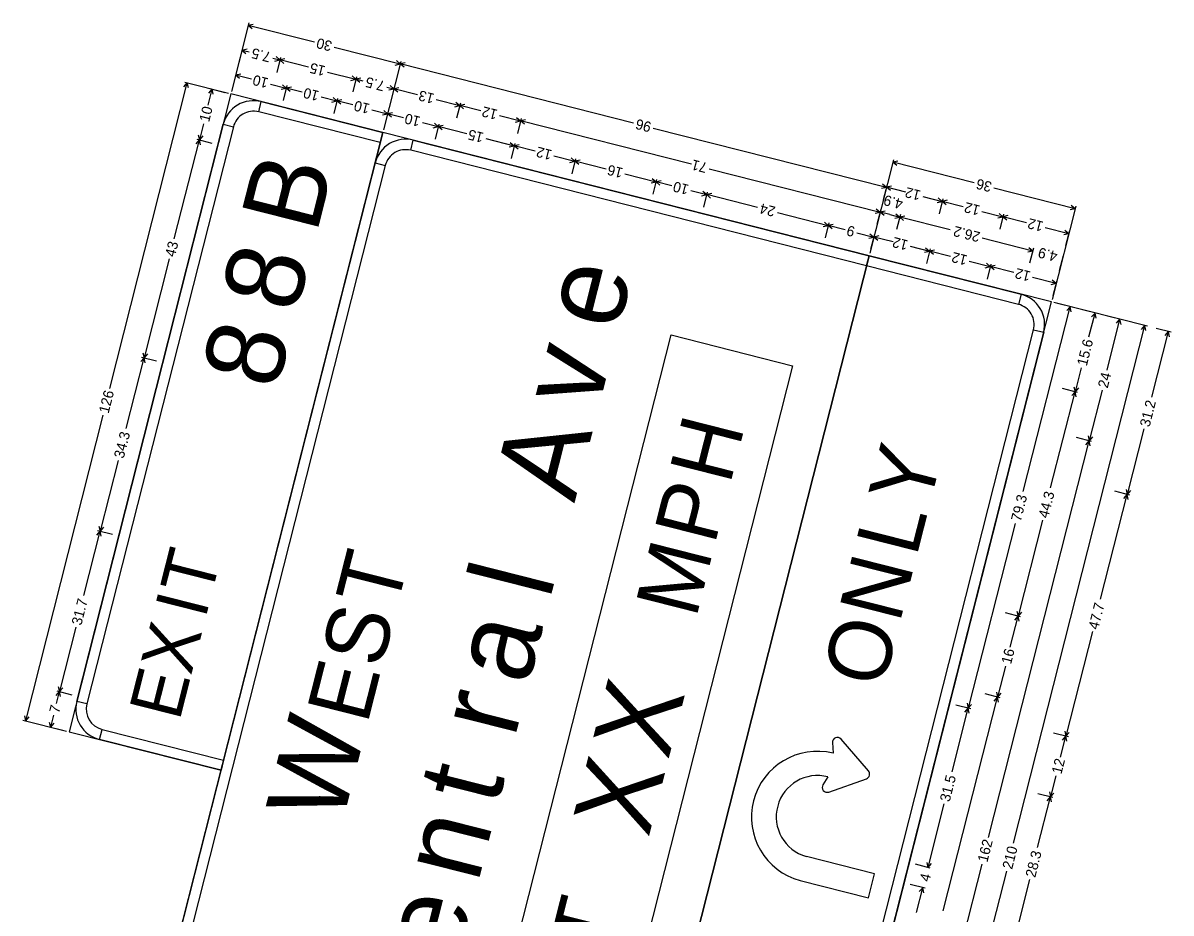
# Model space of a CAD drawing. Extents: x 670003 to 670131, y 737764 to 738002.
# Drawn here: x 670003.1 to 670058, y 737872.3 to 737914.9 of the extents above; entities that cross this region are included whole.
import ezdxf

# ---------------------------------------------------------------- set-up
doc = ezdxf.new("R2010")
doc.units = 0
doc.layers.add('R_SIGN', color=7, linetype='Continuous')

msp = doc.modelspace()

# ---------------------------------------------------------------- linework, layer by layer
at = {"layer": 'R_SIGN'}
for p, q in [((670013.91, 737914.946), (670013.078, 737911.666)), ((670014.12, 737914.879), (670013.88, 737914.826)), ((670017.044, 737914.024), (670013.88, 737914.826)), ((670014.066, 737914.666), (670013.88, 737914.826)), ((670013.608, 737913.753), (670013.426, 737913.038)), ((670013.818, 737913.686), (670013.577, 737913.634)), ((670013.917, 737913.548), (670013.577, 737913.634)), ((670013.764, 737913.473), (670013.577, 737913.634)), ((670017.986, 737913.785), (670021.15, 737912.982)), ((670015.055, 737913.259), (670015.395, 737913.173)), ((670015.155, 737913.12), (670015.395, 737913.173)), ((670015.209, 737913.334), (670015.395, 737913.173)), ((670015.425, 737913.292), (670015.244, 737912.577)), ((670015.635, 737913.225), (670015.395, 737913.173)), ((670016.761, 737912.826), (670015.395, 737913.173)), ((670015.581, 737913.012), (670015.395, 737913.173)), ((670021.18, 737913.102), (670020.348, 737909.822)), ((670021.18, 737913.102), (670020.348, 737909.822)), ((670020.909, 737912.93), (670021.15, 737912.982)), ((670020.964, 737913.143), (670021.15, 737912.982)), ((670021.39, 737913.035), (670021.15, 737912.982)), ((670032.305, 737910.153), (670021.15, 737912.982)), ((670021.336, 737912.822), (670021.15, 737912.982)), ((670013.305, 737912.561), (670013.124, 737911.845)), ((670013.515, 737912.494), (670013.275, 737912.441)), ((670014.036, 737912.248), (670013.275, 737912.441)), ((670013.461, 737912.281), (670013.275, 737912.441)), ((670017.664, 737912.597), (670019.03, 737912.251)), ((670007.253, 737897.455), (670010.961, 737912.076)), ((670010.801, 737911.89), (670010.961, 737912.076)), ((670010.842, 737912.106), (670012.929, 737911.577)), ((670011.014, 737911.836), (670010.961, 737912.076)), ((670014.937, 737912.02), (670015.698, 737911.827)), ((670015.512, 737911.987), (670015.698, 737911.827)), ((670015.729, 737911.946), (670015.547, 737911.23)), ((670015.939, 737911.879), (670015.698, 737911.827)), ((670018.79, 737912.198), (670019.03, 737912.251)), ((670018.844, 737912.412), (670019.03, 737912.251)), ((670019.06, 737912.37), (670018.879, 737911.655)), ((670019.06, 737912.37), (670018.879, 737911.655)), ((670019.27, 737912.303), (670019.03, 737912.251)), ((670019.37, 737912.165), (670019.03, 737912.251)), ((670019.216, 737912.09), (670019.03, 737912.251)), ((670020.507, 737911.876), (670020.847, 737911.79)), ((670020.661, 737911.951), (670020.847, 737911.79)), ((670020.878, 737911.909), (670020.696, 737911.194)), ((670020.878, 737911.909), (670020.696, 737911.194)), ((670013.048, 737911.547), (670005.304, 737881.014)), ((670011.961, 737911.012), (670012.154, 737911.774)), ((670011.993, 737911.587), (670012.154, 737911.774)), ((670012.035, 737911.804), (670012.75, 737911.622)), ((670012.206, 737911.533), (670012.154, 737911.774)), ((670020.318, 737909.703), (670013.048, 737911.547)), ((670015.458, 737911.774), (670015.698, 737911.827)), ((670016.46, 737911.634), (670015.698, 737911.827)), ((670015.885, 737911.666), (670015.698, 737911.827)), ((670017.36, 737911.405), (670018.122, 737911.212)), ((670017.935, 737911.373), (670018.122, 737911.212)), ((670018.152, 737911.331), (670017.97, 737910.616)), ((670018.152, 737911.331), (670017.97, 737910.616)), ((670020.607, 737911.737), (670020.847, 737911.79)), ((670021.088, 737911.843), (670020.847, 737911.79)), ((670021.971, 737911.505), (670020.847, 737911.79)), ((670021.034, 737911.629), (670020.847, 737911.79)), ((670014.379, 737910.693), (670014.502, 737911.178)), ((670017.881, 737911.16), (670018.122, 737911.212)), ((670018.362, 737911.265), (670018.122, 737911.212)), ((670018.883, 737911.019), (670018.122, 737911.212)), ((670018.308, 737911.051), (670018.122, 737911.212)), ((670019.783, 737910.791), (670020.545, 737910.597)), ((670022.874, 737911.276), (670023.998, 737910.991)), ((670023.757, 737910.938), (670023.998, 737910.991)), ((670023.811, 737911.152), (670023.998, 737910.991)), ((670024.028, 737911.11), (670023.846, 737910.395)), ((670024.238, 737911.044), (670023.998, 737910.991)), ((670025.002, 737910.736), (670023.998, 737910.991)), ((670024.184, 737910.83), (670023.998, 737910.991)), ((670020.305, 737910.545), (670020.545, 737910.597)), ((670020.359, 737910.758), (670020.545, 737910.597)), ((670020.575, 737910.717), (670020.394, 737910.001)), ((670020.575, 737910.717), (670020.394, 737910.001)), ((670020.785, 737910.65), (670020.545, 737910.597)), ((670021.306, 737910.404), (670020.545, 737910.597)), ((670020.731, 737910.437), (670020.545, 737910.597)), ((670025.901, 737910.508), (670026.905, 737910.253)), ((670026.665, 737910.201), (670026.905, 737910.253)), ((670026.719, 737910.414), (670026.905, 737910.253)), ((670026.936, 737910.373), (670026.754, 737909.657)), ((670026.936, 737910.373), (670026.754, 737909.657)), ((670027.146, 737910.306), (670026.905, 737910.253)), ((670035.084, 737908.179), (670026.905, 737910.253)), ((670027.092, 737910.093), (670026.905, 737910.253)), ((670020.318, 737909.703), (670007.411, 737858.814)), ((670011.732, 737910.112), (670011.539, 737909.35)), ((670012.574, 737879.17), (670020.318, 737909.703)), ((670012.679, 737910.093), (670013.164, 737909.97)), ((670043.581, 737903.803), (670020.318, 737909.703)), ((670022.207, 737910.176), (670022.968, 737909.983)), ((670022.728, 737909.93), (670022.968, 737909.983)), ((670022.782, 737910.144), (670022.968, 737909.983)), ((670022.998, 737910.102), (670022.817, 737909.387)), ((670023.208, 737910.035), (670022.968, 737909.983)), ((670024.334, 737909.636), (670022.968, 737909.983)), ((670023.154, 737909.822), (670022.968, 737909.983)), ((670033.258, 737909.912), (670044.413, 737907.082)), ((670010.339, 737904.618), (670011.539, 737909.35)), ((670011.378, 737909.164), (670011.539, 737909.35)), ((670011.42, 737909.381), (670012.136, 737909.199)), ((670011.42, 737909.381), (670012.136, 737909.199)), ((670011.487, 737909.591), (670011.539, 737909.35)), ((670011.7, 737909.537), (670011.539, 737909.35)), ((670011.592, 737909.11), (670011.539, 737909.35)), ((670021.649, 737908.85), (670021.772, 737909.334)), ((670025.237, 737909.407), (670026.603, 737909.061)), ((670026.417, 737909.222), (670026.603, 737909.061)), ((670026.633, 737909.18), (670026.452, 737908.465)), ((670026.363, 737909.008), (670026.603, 737909.061)), ((670026.843, 737909.114), (670026.603, 737909.061)), ((670027.608, 737908.806), (670026.603, 737909.061)), ((670026.789, 737908.9), (670026.603, 737909.061)), ((670028.506, 737908.578), (670029.511, 737908.323)), ((670019.949, 737908.249), (670020.434, 737908.126)), ((670029.271, 737908.271), (670029.511, 737908.323)), ((670029.325, 737908.484), (670029.511, 737908.323)), ((670029.541, 737908.443), (670029.36, 737907.727)), ((670029.751, 737908.376), (670029.511, 737908.323)), ((670030.996, 737907.947), (670029.511, 737908.323)), ((670029.697, 737908.163), (670029.511, 737908.323)), ((670044.746, 737908.394), (670043.612, 737903.922)), ((670044.956, 737908.328), (670044.716, 737908.275)), ((670048.602, 737907.289), (670044.716, 737908.275)), ((670044.902, 737908.114), (670044.716, 737908.275)), ((670031.903, 737907.717), (670033.388, 737907.34)), ((670033.202, 737907.501), (670033.388, 737907.34)), ((670035.932, 737907.964), (670044.111, 737905.89)), ((670033.148, 737907.288), (670033.388, 737907.34)), ((670033.418, 737907.459), (670033.237, 737906.744)), ((670033.629, 737907.393), (670033.388, 737907.34)), ((670034.15, 737907.147), (670033.388, 737907.34)), ((670033.574, 737907.179), (670033.388, 737907.34)), ((670044.443, 737907.202), (670043.612, 737903.922)), ((670044.173, 737907.03), (670044.413, 737907.082)), ((670044.227, 737907.243), (670044.413, 737907.082)), ((670044.443, 737907.202), (670044.262, 737906.486)), ((670044.654, 737907.135), (670044.413, 737907.082)), ((670045.343, 737906.846), (670044.413, 737907.082)), ((670044.599, 737906.922), (670044.413, 737907.082)), ((670049.553, 737907.048), (670053.439, 737906.063)), ((670035.05, 737906.919), (670035.811, 737906.726)), ((670035.571, 737906.673), (670035.811, 737906.726)), ((670035.625, 737906.886), (670035.811, 737906.726)), ((670035.842, 737906.845), (670035.66, 737906.129)), ((670036.052, 737906.778), (670035.811, 737906.726)), ((670038.244, 737906.109), (670035.811, 737906.726)), ((670035.998, 737906.565), (670035.811, 737906.726)), ((670046.149, 737906.642), (670047.079, 737906.406)), ((670046.839, 737906.354), (670047.079, 737906.406)), ((670046.893, 737906.567), (670047.079, 737906.406)), ((670047.109, 737906.526), (670046.928, 737905.81)), ((670047.319, 737906.459), (670047.079, 737906.406)), ((670048.084, 737906.151), (670047.079, 737906.406)), ((670047.265, 737906.246), (670047.079, 737906.406)), ((670039.195, 737905.867), (670041.627, 737905.25)), ((670043.87, 737905.837), (670044.111, 737905.89)), ((670043.925, 737906.051), (670044.111, 737905.89)), ((670044.141, 737906.009), (670043.96, 737905.294)), ((670044.141, 737906.009), (670043.96, 737905.294)), ((670044.351, 737905.942), (670044.111, 737905.89)), ((670044.58, 737905.771), (670044.111, 737905.89)), ((670044.297, 737905.729), (670044.111, 737905.89)), ((670048.982, 737905.924), (670049.987, 737905.669)), ((670049.801, 737905.83), (670049.987, 737905.669)), ((670053.47, 737906.182), (670052.335, 737901.71)), ((670053.199, 737906.01), (670053.439, 737906.063)), ((670053.253, 737906.223), (670053.439, 737906.063)), ((670041.441, 737905.411), (670041.627, 737905.25)), ((670041.658, 737905.37), (670041.476, 737904.654)), ((670041.658, 737905.37), (670041.476, 737904.654)), ((670041.868, 737905.303), (670041.627, 737905.25)), ((670044.58, 737905.771), (670045.05, 737905.652)), ((670044.809, 737905.599), (670045.05, 737905.652)), ((670044.863, 737905.812), (670045.05, 737905.652)), ((670045.08, 737905.771), (670044.898, 737905.056)), ((670045.29, 737905.704), (670045.05, 737905.652)), ((670047.468, 737905.038), (670045.05, 737905.652)), ((670045.236, 737905.491), (670045.05, 737905.652)), ((670049.746, 737905.616), (670049.987, 737905.669)), ((670050.017, 737905.788), (670049.836, 737905.073)), ((670050.017, 737905.788), (670049.836, 737905.073)), ((670050.227, 737905.722), (670049.987, 737905.669)), ((670051.11, 737905.384), (670049.987, 737905.669)), ((670050.173, 737905.508), (670049.987, 737905.669)), ((670041.387, 737905.198), (670041.627, 737905.25)), ((670042.435, 737905.046), (670041.627, 737905.25)), ((670041.814, 737905.09), (670041.627, 737905.25)), ((670043.001, 737904.902), (670043.808, 737904.697)), ((670043.622, 737904.858), (670043.808, 737904.697)), ((670043.839, 737904.817), (670043.657, 737904.101)), ((670043.839, 737904.817), (670043.657, 737904.101)), ((670044.049, 737904.75), (670043.808, 737904.697)), ((670052.013, 737905.155), (670053.137, 737904.87)), ((670052.897, 737904.817), (670053.137, 737904.87)), ((670052.951, 737905.031), (670053.137, 737904.87)), ((670053.167, 737904.989), (670052.986, 737904.274)), ((670043.568, 737904.645), (670043.808, 737904.697)), ((670044.738, 737904.461), (670043.808, 737904.697)), ((670043.995, 737904.537), (670043.808, 737904.697)), ((670045.544, 737904.257), (670046.474, 737904.021)), ((670046.288, 737904.182), (670046.474, 737904.021)), ((670048.993, 737904.652), (670051.411, 737904.038)), ((670051.225, 737904.199), (670051.411, 737904.038)), ((670010.093, 737903.65), (670008.893, 737898.918)), ((670030.675, 737852.914), (670043.581, 737903.803)), ((670043.581, 737903.803), (670030.675, 737852.914)), ((670052.305, 737901.59), (670043.581, 737903.803)), ((670046.234, 737903.969), (670046.474, 737904.021)), ((670046.504, 737904.14), (670046.323, 737903.425)), ((670046.714, 737904.074), (670046.474, 737904.021)), ((670047.479, 737903.766), (670046.474, 737904.021)), ((670046.66, 737903.861), (670046.474, 737904.021)), ((670051.171, 737903.986), (670051.411, 737904.038)), ((670051.441, 737904.158), (670051.26, 737903.442)), ((670051.441, 737904.158), (670051.26, 737903.442)), ((670052.865, 737903.796), (670052.683, 737903.081)), ((670048.377, 737903.539), (670049.382, 737903.284)), ((670049.142, 737903.231), (670049.382, 737903.284)), ((670049.196, 737903.444), (670049.382, 737903.284)), ((670049.412, 737903.403), (670049.231, 737902.687)), ((670049.412, 737903.403), (670049.231, 737902.687)), ((670049.622, 737903.336), (670049.382, 737903.284)), ((670050.506, 737902.999), (670049.382, 737903.284)), ((670049.568, 737903.123), (670049.382, 737903.284)), ((670051.408, 737902.77), (670052.532, 737902.485)), ((670052.346, 737902.645), (670052.532, 737902.485)), ((670052.562, 737902.604), (670052.381, 737901.888)), ((670052.292, 737902.432), (670052.532, 737902.485)), ((670039.399, 737850.702), (670052.305, 737901.59)), ((670050.851, 737901.959), (670050.728, 737901.474)), ((670056.897, 737900.426), (670052.424, 737901.56)), ((670053.319, 737901.333), (670052.603, 737901.515)), ((670050.955, 737892.512), (670053.2, 737901.363)), ((670053.039, 737901.177), (670053.2, 737901.363)), ((670053.252, 737901.123), (670053.2, 737901.363)), ((670054.511, 737901.031), (670053.796, 737901.212)), ((670054.102, 737899.917), (670054.392, 737901.061)), ((670054.231, 737900.875), (670054.392, 737901.061)), ((670054.445, 737900.821), (670054.392, 737901.061)), ((670055.704, 737900.728), (670054.989, 737900.91)), ((670050.493, 737875.679), (670056.777, 737900.456)), ((670054.968, 737898.326), (670055.585, 737900.759)), ((670055.424, 737900.572), (670055.585, 737900.759)), ((670055.637, 737900.518), (670055.585, 737900.759)), ((670056.617, 737900.27), (670056.777, 737900.456)), ((670056.83, 737900.216), (670056.777, 737900.456)), ((670024.153, 737860.758), (670034.11, 737900.015)), ((670034.11, 737900.015), (670039.925, 737898.54)), ((670051.452, 737900.259), (670051.936, 737900.136)), ((670057.114, 737897.029), (670057.91, 737900.169)), ((670058.03, 737900.139), (670057.314, 737900.32)), ((670057.75, 737899.983), (670057.91, 737900.169)), ((670057.963, 737899.928), (670057.91, 737900.169)), ((670008.034, 737895.528), (670008.893, 737898.918)), ((670008.733, 737898.732), (670008.893, 737898.918)), ((670008.774, 737898.948), (670009.49, 737898.767)), ((670008.841, 737899.159), (670008.893, 737898.918)), ((670009.054, 737899.104), (670008.893, 737898.918)), ((670008.946, 737898.678), (670008.893, 737898.918)), ((670039.925, 737898.54), (670029.969, 737859.283)), ((670053.726, 737898.435), (670053.436, 737897.29)), ((670052.269, 737892.692), (670053.436, 737897.29)), ((670053.555, 737897.26), (670052.84, 737897.442)), ((670053.555, 737897.26), (670052.84, 737897.442)), ((670053.275, 737897.104), (670053.436, 737897.29)), ((670053.383, 737897.531), (670053.436, 737897.29)), ((670053.597, 737897.477), (670053.436, 737897.29)), ((670053.488, 737897.05), (670053.436, 737897.29)), ((670054.727, 737897.375), (670054.11, 737894.943)), ((670006.926, 737896.164), (670003.217, 737881.543)), ((670056.73, 737895.514), (670055.933, 737892.375)), ((670049.294, 737875.954), (670054.11, 737894.943)), ((670054.229, 737894.912), (670053.514, 737895.094)), ((670054.229, 737894.912), (670053.514, 737895.094)), ((670053.949, 737894.757), (670054.11, 737894.943)), ((670054.057, 737895.183), (670054.11, 737894.943)), ((670054.271, 737895.129), (670054.11, 737894.943)), ((670054.162, 737894.702), (670054.11, 737894.943)), ((670007.648, 737894.008), (670006.788, 737890.618)), ((670054.661, 737887.358), (670055.933, 737892.375)), ((670056.053, 737892.344), (670055.337, 737892.526)), ((670056.053, 737892.344), (670055.337, 737892.526)), ((670055.773, 737892.188), (670055.933, 737892.375)), ((670055.881, 737892.615), (670055.933, 737892.375)), ((670056.094, 737892.561), (670055.933, 737892.375)), ((670055.986, 737892.134), (670055.933, 737892.375)), ((670051.878, 737891.149), (670050.712, 737886.55)), ((670006.007, 737887.536), (670006.788, 737890.618)), ((670006.628, 737890.432), (670006.788, 737890.618)), ((670006.669, 737890.649), (670007.385, 737890.467)), ((670006.736, 737890.859), (670006.788, 737890.618)), ((670006.949, 737890.805), (670006.788, 737890.618)), ((670006.841, 737890.378), (670006.788, 737890.618)), ((670050.569, 737890.992), (670048.324, 737882.14)), ((670050.831, 737886.52), (670050.116, 737886.702)), ((670050.659, 737886.791), (670050.712, 737886.55)), ((670050.873, 737886.737), (670050.712, 737886.55)), ((670050.335, 737885.066), (670050.712, 737886.55)), ((670050.551, 737886.364), (670050.712, 737886.55)), ((670050.765, 737886.31), (670050.712, 737886.55)), ((670005.622, 737886.019), (670004.84, 737882.937)), ((670054.271, 737885.818), (670052.998, 737880.801)), ((670050.105, 737884.158), (670049.729, 737882.673)), ((670004.679, 737882.75), (670004.84, 737882.937)), ((670004.696, 737882.369), (670004.84, 737882.937)), ((670004.721, 737882.967), (670005.436, 737882.785)), ((670004.787, 737883.177), (670004.84, 737882.937)), ((670005.001, 737883.123), (670004.84, 737882.937)), ((670004.893, 737882.696), (670004.84, 737882.937)), ((670049.848, 737882.643), (670049.132, 737882.824)), ((670049.676, 737882.914), (670049.729, 737882.673)), ((670049.889, 737882.859), (670049.729, 737882.673)), ((670006.158, 737882.345), (670005.673, 737882.468)), ((670047.134, 737872.441), (670049.729, 737882.673)), ((670048.443, 737882.109), (670047.728, 737882.291)), ((670048.443, 737882.109), (670047.728, 737882.291)), ((670048.272, 737882.38), (670048.324, 737882.14)), ((670048.485, 737882.326), (670048.324, 737882.14)), ((670049.568, 737882.487), (670049.729, 737882.673)), ((670049.781, 737882.433), (670049.729, 737882.673)), ((670003.165, 737881.783), (670003.217, 737881.543)), ((670003.378, 737881.729), (670003.217, 737881.543)), ((670004.554, 737881.808), (670004.41, 737881.24)), ((670047.551, 737879.09), (670048.324, 737882.14)), ((670048.163, 737881.953), (670048.324, 737882.14)), ((670048.377, 737881.899), (670048.324, 737882.14)), ((670003.098, 737881.573), (670005.185, 737881.044)), ((670004.291, 737881.271), (670005.006, 737881.089)), ((670004.357, 737881.481), (670004.41, 737881.24)), ((670004.571, 737881.427), (670004.41, 737881.24)), ((670006.758, 737880.645), (670006.881, 737881.129)), ((670005.304, 737881.014), (670012.574, 737879.17)), ((670043.551, 737879.144), (670042.241, 737880.663)), ((670043.551, 737879.144), (670042.241, 737880.663)), ((670053.117, 737880.771), (670052.402, 737880.952)), ((670052.743, 737879.796), (670052.998, 737880.801)), ((670052.837, 737880.615), (670052.998, 737880.801)), ((670052.946, 737881.041), (670052.998, 737880.801)), ((670053.159, 737880.987), (670052.998, 737880.801)), ((670053.051, 737880.56), (670052.998, 737880.801)), ((670041.828, 737880.496), (670041.857, 737879.985)), ((670041.828, 737880.496), (670041.857, 737879.985)), ((670012.574, 737879.17), (670012.574, 737879.17)), ((670041.612, 737878.854), (670041.374, 737878.48)), ((670041.612, 737878.854), (670041.374, 737878.48)), ((670041.651, 737878.131), (670043.451, 737878.768)), ((670041.651, 737878.131), (670043.451, 737878.768)), ((670052.516, 737878.898), (670052.261, 737877.893)), ((670051.648, 737875.477), (670052.261, 737877.893)), ((670052.38, 737877.863), (670051.664, 737878.044)), ((670052.1, 737877.707), (670052.261, 737877.893)), ((670052.208, 737878.133), (670052.261, 737877.893)), ((670052.421, 737878.079), (670052.261, 737877.893)), ((670052.313, 737877.653), (670052.261, 737877.893)), ((670047.165, 737877.57), (670046.392, 737874.521)), ((670043.847, 737874.215), (670040.581, 737875.044)), ((670043.847, 737874.215), (670040.581, 737875.044)), ((670048.969, 737874.674), (670044.153, 737855.686)), ((670046.511, 737874.491), (670045.795, 737874.672)), ((670046.339, 737874.761), (670046.392, 737874.521)), ((670046.552, 737874.707), (670046.392, 737874.521)), ((670043.555, 737873.062), (670043.847, 737874.215)), ((670043.555, 737873.062), (670043.847, 737874.215)), ((670050.155, 737874.344), (670043.871, 737849.567)), ((670040.289, 737873.89), (670043.555, 737873.062)), ((670040.289, 737873.89), (670043.555, 737873.062)), ((670046.265, 737873.521), (670045.55, 737873.703)), ((670045.845, 737872.364), (670046.146, 737873.552)), ((670045.985, 737873.365), (670046.146, 737873.552)), ((670046.198, 737873.311), (670046.146, 737873.552)), ((670051.26, 737873.947), (670050.647, 737871.531))]:
    msp.add_line(p, q, dxfattribs=at)
for points in [[(670020.195, 737909.218), (670014.379, 737910.693), (670014.502, 737911.178), (670020.318, 737909.703), (670020.195, 737909.218)], [(670013.164, 737909.97), (670006.158, 737882.345), (670005.673, 737882.468), (670012.679, 737910.093), (670013.164, 737909.97)], [(670043.459, 737903.318), (670021.649, 737908.85), (670021.772, 737909.334), (670043.581, 737903.803), (670043.459, 737903.318)], [(670020.434, 737908.126), (670008.265, 737860.145), (670007.78, 737860.268), (670019.949, 737908.249), (670020.434, 737908.126)], [(670050.728, 737901.474), (670043.459, 737903.318), (670043.581, 737903.803), (670050.851, 737901.959), (670050.728, 737901.474)], [(670039.283, 737852.278), (670051.452, 737900.259), (670051.936, 737900.136), (670039.767, 737852.156), (670039.283, 737852.278)], [(670006.881, 737881.129), (670012.697, 737879.654), (670012.574, 737879.17), (670006.758, 737880.645), (670006.881, 737881.129)]]:
    msp.add_lwpolyline(points, close=True, dxfattribs=at)
for centre, radius, start, end in [((670014.133, 737909.724), 1.5, 75.7686, 165.7688), ((670014.133, 737909.724), 1, 75.7686, 165.7688), ((670021.403, 737907.88), 1.5, 75.7686, 165.7688), ((670021.403, 737907.88), 1, 75.7686, 165.7688), ((670050.483, 737900.505), 1, 345.7686, 75.7688), ((670050.483, 737900.505), 1.5, 345.7686, 75.7688), ((670007.127, 737882.099), 1.5, 165.7688, 255.7684), ((670007.127, 737882.099), 1, 165.7688, 255.7684), ((670042.063, 737880.509), 0.235, 40.7767, 183.2283), ((670042.063, 737880.509), 0.235, 40.7767, 183.2283), ((670041.104, 737876.93), 3.147, 76.1684, 254.9793), ((670041.104, 737876.93), 3.147, 76.1684, 254.9793), ((670041.114, 737876.944), 1.974, 75.3868, 254.3334), ((670041.114, 737876.944), 1.974, 75.3868, 254.3334), ((670043.373, 737878.99), 0.235, 289.4736, 40.7767), ((670043.373, 737878.99), 0.235, 289.4736, 40.7767), ((670041.573, 737878.353), 0.235, 147.5362, 289.4736), ((670041.573, 737878.353), 0.235, 147.5362, 289.4736)]:
    msp.add_arc(centre, radius, start, end, dxfattribs=at)

# ---------------------------------------------------------------- texts
for s, height, rotation, p in [('30', 0.4921, 165.7688, (670017.927, 737914.054)), ('7.5', 0.4921, 165.7688, (670014.996, 737913.528)), ('15', 0.4921, 165.7688, (670017.605, 737912.866)), ('10', 0.4921, 165.7688, (670014.878, 737912.288)), ('7.5', 0.4921, 165.7688, (670020.449, 737912.145)), ('10', 0.4921, 165.7688, (670017.301, 737911.674)), ('13', 0.4921, 165.7688, (670022.815, 737911.545)), ('10', 0.4921, 75.7686, (670012.001, 737910.171)), ('10', 0.4921, 165.7688, (670019.725, 737911.059)), ('12', 0.4921, 165.7688, (670025.842, 737910.777)), ('10', 0.4921, 165.7688, (670022.148, 737910.445)), ('96', 0.4921, 165.7688, (670033.199, 737910.18)), ('15', 0.4921, 165.7688, (670025.178, 737909.676)), ('12', 0.4921, 165.7688, (670028.447, 737908.847)), ('B', 3.75, 75.7686, (670017.139, 737904.796)), ('16', 0.4921, 165.7688, (670031.845, 737907.985)), ('71', 0.4921, 165.7688, (670035.873, 737908.233)), ('36', 0.4921, 165.7688, (670049.494, 737907.317)), ('10', 0.4921, 165.7688, (670034.991, 737907.187)), ('12', 0.4921, 165.7688, (670046.09, 737906.911)), ('4.9', 0.4921, 165.7688, (670045.241, 737906.492)), ('24', 0.4921, 165.7688, (670039.136, 737906.136)), ('12', 0.4921, 165.7688, (670048.923, 737906.193)), ('12', 0.4921, 165.7688, (670051.955, 737905.424)), ('9', 0.492, 165.7688, (670042.942, 737905.171)), ('26.2', 0.4921, 165.7688, (670048.934, 737904.92)), ('43', 0.4921, 75.7686, (670010.362, 737903.709)), ('8', 3.75, 75.7686, (670016.171, 737900.98)), ('12', 0.4921, 165.7688, (670045.485, 737904.526)), ('4.9', 0.4921, 165.7688, (670052.634, 737903.982)), ('12', 0.4921, 165.7688, (670048.318, 737903.807)), ('e', 4, 75.7686, (670031.556, 737900.116)), ('12', 0.4921, 165.7688, (670051.35, 737903.038)), ('8', 3.75, 75.7686, (670015.24, 737897.309)), ('15.6', 0.4921, 75.7686, (670053.995, 737898.493)), ('v', 4, 75.7686, (670030.602, 737896.355)), ('24', 0.4921, 75.7686, (670054.996, 737897.434)), ('126', 0.4921, 75.7686, (670007.194, 737896.223)), ('31.2', 0.4921, 75.7686, (670056.999, 737895.573)), ('H', 3, 75.7686, (670036.921, 737892.795)), ('34.3', 0.4921, 75.7686, (670007.917, 737894.067)), ('A', 4, 75.7686, (670029.481, 737891.935)), ('Y', 3, 75.7686, (670046.433, 737891.658)), ('P', 3, 75.7686, (670036.191, 737889.916)), ('79.3', 0.4921, 75.7686, (670050.838, 737891.05)), ('44.3', 0.4921, 75.7686, (670052.147, 737891.208)), ('L', 3, 75.7686, (670045.843, 737889.332)), ('M', 3, 75.7686, (670035.298, 737886.398)), ('T', 2.5, 75.7686, (670012.074, 737887.369)), ('T', 3, 75.7686, (670020.955, 737886.791)), ('N', 3, 75.7686, (670045.039, 737886.162)), ('l', 4, 75.7686, (670028.301, 737887.282)), ('31.7', 0.4921, 75.7686, (670005.89, 737886.078)), ('I', 2.5, 75.7686, (670011.822, 737886.374)), ('47.7', 0.4921, 75.7686, (670054.539, 737885.877)), ('S', 3, 75.7686, (670020.247, 737883.999)), ('X', 2.5, 75.7686, (670011.136, 737883.671)), ('a', 4, 75.7686, (670027.259, 737883.173)), ('O', 3, 75.7686, (670044.243, 737883.022)), ('16', 0.4921, 75.7686, (670050.374, 737884.217)), ('E', 3, 75.7686, (670019.568, 737881.324)), ('E', 2.5, 75.7686, (670010.581, 737881.481)), ('X', 3.75, 75.7686, (670033.966, 737879.617)), ('r', 4, 75.7686, (670026.62, 737880.652)), ('7', 0.492, 75.7686, (670004.822, 737881.867)), ('W', 3.75, 75.7686, (670018.345, 737876.502)), ('t', 4, 75.7686, (670025.794, 737877.395)), ('X', 3.75, 75.7686, (670033.025, 737875.91)), ('12', 0.4921, 75.7686, (670052.784, 737878.957)), ('31.5', 0.4921, 75.7686, (670047.434, 737877.629)), ('n', 4, 75.7686, (670024.859, 737873.712)), ('162', 0.4921, 75.7686, (670049.238, 737874.733)), ('210', 0.4921, 75.7686, (670050.424, 737874.403)), ('28.3', 0.4921, 75.7686, (670051.529, 737874.006)), ('4', 0.492, 75.7686, (670046.464, 737873.805)), ('e', 4, 75.7686, (670023.906, 737869.951)), ('T', 3, 75.7686, (670031.194, 737870.215))]:
    msp.add_text(s, height=height, rotation=rotation, dxfattribs=at).set_placement(p)

doc.saveas('drawing.dxf')
